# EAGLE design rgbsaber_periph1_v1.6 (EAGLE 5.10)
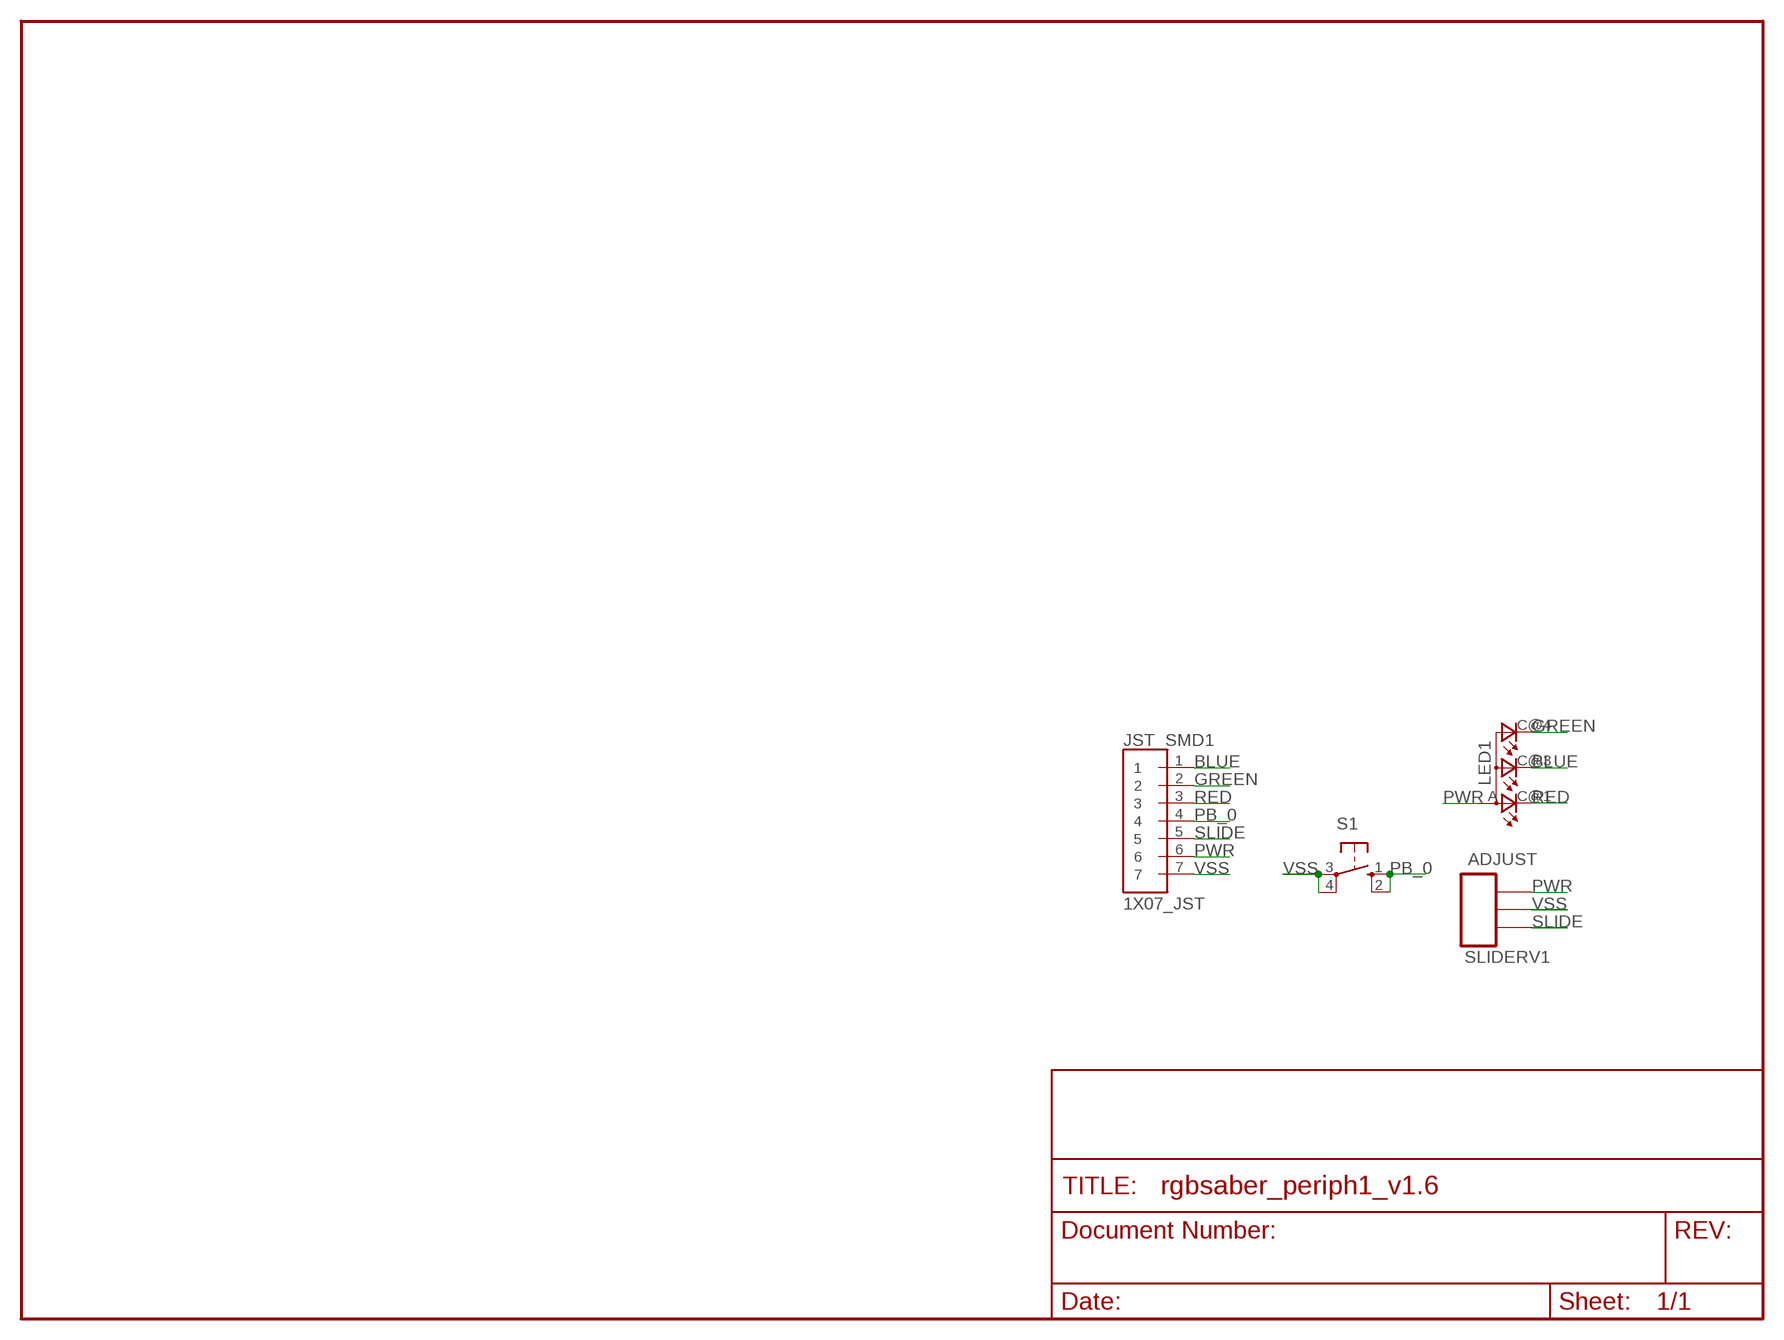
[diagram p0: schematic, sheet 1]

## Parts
ADJUST  SLIDERV1  [SLIDER-CUSTOM]
JST_SMD1  1X07_JST  [JST_ZH_SM4_TE_7]
LED1  LED_RGB_SMDP-LCC-4  [PLCC4]
S1  40-XX  [B3F-40XX]

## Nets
BLUE: JST_SMD1.1 LED1.C@3(CBLUE)
GREEN: JST_SMD1.2 LED1.C@4(CGREEN)
PB_0: JST_SMD1.4 S1.1(S) S1.2(S1)
PWR: ADJUST.P$1 JST_SMD1.6 LED1.A(A2)
RED: JST_SMD1.3 LED1.C@1(CRED)
SLIDE: ADJUST.P$3 JST_SMD1.5
VSS: ADJUST.P$2 JST_SMD1.7 S1.3(P) S1.4(P1)

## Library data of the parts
ADJUST = purduecer:SLIDER: Sliding Potentiometer
JST_SMD1 = NBitWonder:1X07_JST
LED1 = NBitWonder:LED_RGB_SMD: Device for Cree CLV1A-FKB RGB LED. For more information on this part, see www.cree.com/products/pdf/ledlamps/CLV1A-FKB(874).pdf
S1 = switch-omron:40-XX: OMRON SWITCH

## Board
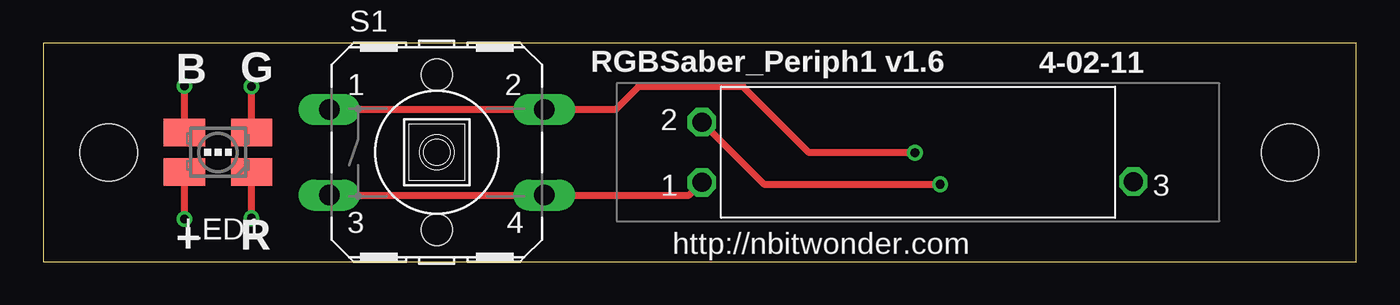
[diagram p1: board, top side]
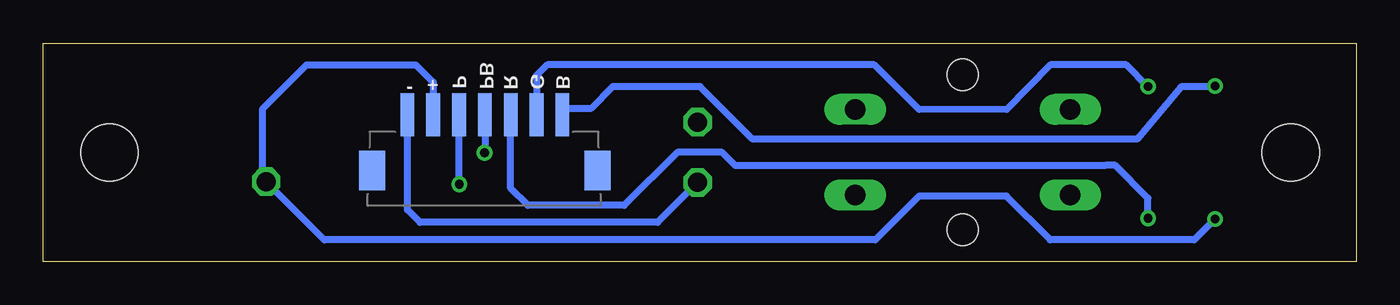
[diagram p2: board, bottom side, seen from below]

Size 76.25 x 12.69 mm. Coordinates in mm from the lower left corner, seen from the top.
Outline: 0,0 76.25,0 76.25,12.69 0,12.69 0,0
Copper layers (1*16): Top 0.035mm / dielectric 1.5mm / Bottom 0.035mm
Design rules "default *": minimum track width 10mil, minimum drill 24mil, track to track 8mil, track to pad 8mil, pad to pad 8mil, via to via 8mil, smd to smd 8mil, copper to edge 40mil, drill to drill 8mil, minimum pad ring 10mil, minimum via ring 8mil, stop-mask expansion 4mil, vias tented up to drill 20mil, thermal gap 10mil

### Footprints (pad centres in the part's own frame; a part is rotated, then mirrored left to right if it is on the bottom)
SLIDER-CUSTOM = drill 1.1 octagon: P$1 -12.5,1.7; P$2 12.55,1.75; P$3 12.55,-1.75
JST_ZH_SM4_TE_7 = smd 0.8 x 2.5: 1 -4.5,-3; 2 -3,-3; 3 -1.5,-3; 4 0,-3; 5 1.5,-3; 6 3,-3; 7 4.5,-3 | smd 1.5 x 2.3: NC0 -6.55,0.25; NC1 6.55,0.25
PLCC4 = smd 1.6 x 2.4: A -1.15,1.95; C@1 -1.15,-1.95; C@3 1.15,1.95; C@4 1.15,-1.95
B3F-40XX = drill 1.194 long: 1 -6.248,2.489; 2 6.248,2.489; 3 -6.248,-2.489; 4 6.248,-2.489 | hole 1.803: 0,-4.496; 0,4.496
STAND-OFF = hole 3.302: 0,0

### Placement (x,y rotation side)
ADJUST  50.8,6.35 180 top
JST_SMD1  50.6,5.54 180 bottom
LED1  10.16,6.35 90 top
S1  22.86,6.35 0 top
U$5  [STAND-OFF]  3.81,6.35 0 top
U$6  [STAND-OFF]  72.39,6.35 90 top

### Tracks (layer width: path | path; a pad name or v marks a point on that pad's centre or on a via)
BLUE  (via drill 0.5)
  Top 0.406: v8.21,10.2 LED1.C@3
  Bottom 0.406: JST_SMD1.1 45.74,8.89 44.45,8.89 43.18,10.16 38.1,10.16 35.06,7.12 12.73,7.12 10.16,10.16 8.25,10.16 v8.21,10.2
GREEN  (via drill 0.5)
  Top 0.406: v12.1,10.16 LED1.C@4
  Bottom 0.406: JST_SMD1.2 47.6,10.8 47.61,10.81 46.99,11.43 27.99,11.43 25.4,8.84 20.31,8.84 17.78,11.43 13.37,11.43 v12.1,10.16
PB_0  (via drill 0.5)
  Top 0.406: S1.1 S1.2 33.23,8.84 34.56,10.16 40.64,10.16 44.47,6.33 v50.62,6.33
  Bottom 0.406: JST_SMD1.4 50.6,6.34 v50.62,6.33
PWR  (via drill 0.5)
  Top 0.406: v8.21,2.48 LED1.A
  Bottom 0.406: 53.6,7.88 JST_SMD1.6 53.6,10.42 54.61,11.43 60.96,11.43 63.5,8.89 63.5,4.85 ADJUST.P$1 59.92,1.27 27.94,1.27 25.4,3.81 20.32,3.81 17.78,1.27 9.43,1.27 v8.21,2.48
RED  (via drill 0.5)
  Top 0.406: v12.11,2.52 LED1.C@1
  Bottom 0.406: JST_SMD1.3 49.1,4.26 48.1,3.27 42.52,3.27 39.43,6.35 36.83,6.35 36.06,5.58 14.59,5.58 14.58,5.58 14.01,5.58 12.11,3.69 v12.11,2.52
SLIDE  (via drill 0.5)
  Top 0.406: v52.08,4.5 41.85,4.5 ADJUST.P$3
  Bottom 0.406: JST_SMD1.5 52.1,4.53 v52.08,4.5
VSS
  Top 0.406: S1.3 S1.4 37.51,3.86 ADJUST.P$2
  Bottom 0.406: JST_SMD1.7 55.1,3.02 54.37,2.29 40.56,2.29 ADJUST.P$2

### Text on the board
tPlace: RGBSaber_Periph1 v1.6 | 4-02-11 | B | G | + | R | http://nbitwonder.com
bPlace: B | G | R | PB | P | + | -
